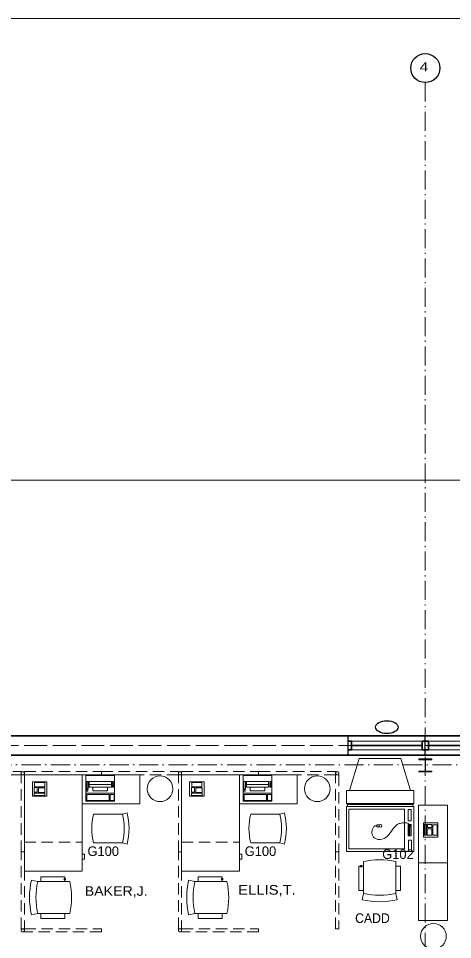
# Model space of a CAD drawing. Extents: x -118748 to -117136, y -118748 to -117596.
# Drawn here: x -118262.8 to -118046.3, y -118056 to -117596.4 of the extents above; entities that cross this region are included whole.
import ezdxf
from ezdxf.enums import TextEntityAlignment as Align

# ---------------------------------------------------------------- set-up
doc = ezdxf.new("R2010")
doc.units = 0
doc.header["$LTSCALE"] = 1.9
doc.header["$PDMODE"] = 32
doc.header["$PDSIZE"] = 0.95
for name, pattern in [('DOT_DASHED', [7.7, 5, -1.2, 0.3, -1.2]), ('LONG_DASHED', [7.5, 6, -1.5]), ('MEDIUM_DASHED', [4.5, 3, -1.5])]:
    doc.linetypes.add(name, pattern=pattern)
for name, color, linetype, lineweight in [('10', 7, 'DOT_DASHED', 13), ('11', 7, 'Continuous', 25), ('12', 7, 'Continuous', 13), ('15', 7, 'Continuous', 13), ('16', 7, 'Continuous', 13), ('2', 7, 'Continuous', 35), ('20', 7, 'MEDIUM_DASHED', 13), ('23', 7, 'Continuous', 25), ('3', 7, 'Continuous', 35), ('30', 7, 'Continuous', 13), ('4', 7, 'Continuous', 35), ('43', 7, 'Continuous', 25), ('5', 7, 'Continuous', 13), ('6', 7, 'Continuous', 13), ('60', 7, 'LONG_DASHED', 13), ('9', 7, 'Continuous', 35)]:
    doc.layers.add(name, color=color, linetype=linetype, lineweight=lineweight)
doc.layers.add('53', color=7, linetype='Continuous')

msp = doc.modelspace()

# ---------------------------------------------------------------- linework, layer by layer
at = {"layer": '10'}
for p, q in [((-118059.921, -117628.339), (-118059.921, -118698.41)), ((-118641.571, -117968.81), (-117285.521, -117968.81))]:
    msp.add_line(p, q, dxfattribs=at)
at = {"layer": '11'}
msp.add_circle((-118059.921, -117621.139), 7.253, dxfattribs=at)
at = {"layer": '12'}
msp.add_lwpolyline([(-118063.104, -117972.362), (-118056.688, -117972.362), (-118056.688, -117971.966), (-118059.772, -117971.966), (-118059.772, -117966.262), (-118056.688, -117966.262), (-118056.688, -117965.866), (-118063.104, -117965.866), (-118063.104, -117966.262), (-118060.02, -117966.262), (-118060.02, -117971.966), (-118063.104, -117971.966)], close=True, dxfattribs=at)
at = {"layer": '15', "lineweight": 25}
for p, q in [((-118098.321, -117954.41), (-118506.321, -117954.41)), ((-118098.321, -117964.01), (-118098.321, -117954.41)), ((-118059.921, -117964.01), (-118059.921, -117954.41)), ((-118059.921, -117964.01), (-118059.921, -117954.41))]:
    msp.add_line(p, q, dxfattribs=at)
at = {"layer": '15'}
for p, q in [((-118225.326, -117993.398), (-118210.926, -117993.398)), ((-118210.926, -117993.398), (-118208.604, -117992.791)), ((-118146.926, -117993.398), (-118132.526, -117993.398)), ((-118132.526, -117993.398), (-118130.204, -117992.791)), ((-118210.926, -118007.798), (-118225.326, -118007.798)), ((-118210.926, -118007.798), (-118208.604, -118008.404)), ((-118132.526, -118007.798), (-118146.926, -118007.798)), ((-118132.526, -118007.798), (-118130.204, -118008.404)), ((-118090.667, -118017.075), (-118090.667, -118033.075)), ((-118074.667, -118017.075), (-118074.667, -118033.075)), ((-118093.067, -118019.475), (-118093.067, -118031.475)), ((-118090.667, -118019.475), (-118093.067, -118019.475)), ((-118090.667, -118019.475), (-118090.667, -118031.475)), ((-118074.667, -118019.475), (-118074.667, -118031.475)), ((-118072.267, -118019.475), (-118074.667, -118019.475)), ((-118072.267, -118019.475), (-118072.267, -118031.475)), ((-118253.199, -118027.04), (-118256.327, -118026.364)), ((-118237.199, -118027.04), (-118253.199, -118027.04)), ((-118239.599, -118024.64), (-118251.599, -118024.64)), ((-118251.599, -118024.64), (-118251.599, -118027.04)), ((-118239.599, -118027.04), (-118251.599, -118027.04)), ((-118239.599, -118027.04), (-118239.599, -118024.64)), ((-118174.799, -118027.04), (-118177.927, -118026.364)), ((-118158.799, -118027.04), (-118174.799, -118027.04)), ((-118161.199, -118024.64), (-118173.199, -118024.64)), ((-118173.199, -118024.64), (-118173.199, -118027.04)), ((-118161.199, -118027.04), (-118173.199, -118027.04)), ((-118161.199, -118027.04), (-118161.199, -118024.64)), ((-118093.067, -118031.475), (-118090.667, -118031.475)), ((-118074.667, -118031.475), (-118072.267, -118031.475)), ((-118090.667, -118033.075), (-118091.343, -118036.203)), ((-118074.667, -118033.075), (-118073.99, -118036.203)), ((-118253.199, -118043.04), (-118256.327, -118043.716)), ((-118237.199, -118043.04), (-118253.199, -118043.04)), ((-118239.599, -118043.04), (-118251.599, -118043.04)), ((-118251.599, -118043.04), (-118251.599, -118045.44)), ((-118239.599, -118045.44), (-118251.599, -118045.44)), ((-118239.599, -118045.44), (-118239.599, -118043.04)), ((-118174.799, -118043.04), (-118177.927, -118043.716)), ((-118158.799, -118043.04), (-118174.799, -118043.04)), ((-118161.199, -118043.04), (-118173.199, -118043.04)), ((-118173.199, -118043.04), (-118173.199, -118045.44)), ((-118161.199, -118045.44), (-118173.199, -118045.44)), ((-118161.199, -118045.44), (-118161.199, -118043.04))]:
    msp.add_line(p, q, dxfattribs=at)
at = {"layer": '15', "lineweight": 25}
msp.add_lwpolyline([(-118098.321, -117964.01), (-118496.721, -117964.01), (-118496.721, -117992.81)], dxfattribs=at)
at = {"layer": '15'}
for points in [[(-118259.812, -118021.839), (-118231.012, -118021.839), (-118231.012, -117973.839), (-118259.812, -117973.839)], [(-118231.012, -117988.239), (-118202.212, -117988.239), (-118202.212, -117973.839), (-118231.012, -117973.839)], [(-118181.412, -118021.839), (-118152.612, -118021.839), (-118152.612, -117973.839), (-118181.412, -117973.839)], [(-118152.612, -117988.239), (-118123.812, -117988.239), (-118123.812, -117973.839), (-118152.612, -117973.839)], [(-118063.307, -117988.887), (-118063.307, -118017.687), (-118048.907, -118017.687), (-118048.907, -117988.887)], [(-118063.307, -118017.687), (-118063.307, -118046.487), (-118048.907, -118046.487), (-118048.907, -118017.687)]]:
    msp.add_lwpolyline(points, close=True, dxfattribs=at)
for centre, radius, start, end in [((-118197.776, -118000.597), 28.475, 165.35367, 194.64632), ((-118238.475, -118000.597), 28.475, 345.35367, 14.64632), ((-118238.475, -118000.597), 30.875, 345.35367, 14.64632), ((-118119.376, -118000.597), 28.475, 165.35367, 194.64632), ((-118160.075, -118000.597), 28.475, 345.35367, 14.64632), ((-118160.075, -118000.597), 30.875, 345.35367, 14.64632), ((-118082.667, -118054.083), 37.863, 77.80217, 102.19783), ((-118216.19, -118035.04), 41.063, 167.80217, 192.19782), ((-118216.19, -118035.04), 37.863, 167.80217, 192.19782), ((-118216.19, -118035.04), 37.863, 167.80217, 192.19782), ((-118274.207, -118035.04), 37.863, 347.80217, 12.19783), ((-118137.79, -118035.04), 41.063, 167.80217, 192.19782), ((-118137.79, -118035.04), 37.863, 167.80217, 192.19782), ((-118137.79, -118035.04), 37.863, 167.80217, 192.19782), ((-118195.807, -118035.04), 37.863, 347.80217, 12.19783), ((-118082.667, -117996.067), 41.063, 257.80217, 282.19783), ((-118082.667, -117996.067), 37.863, 257.80217, 282.19783), ((-118082.667, -117996.067), 37.863, 257.80217, 282.19783)]:
    msp.add_arc(centre, radius, start, end, dxfattribs=at)
for p in [(-118091.867, -118019.475), (-118239.599, -118025.84), (-118161.199, -118025.84)]:
    msp.add_point(p, dxfattribs=at)
at = {"layer": '16'}
for p, q in [((-118098.321, -117954.41), (-118059.921, -117954.41)), ((-118096.721, -117957.027), (-118061.521, -117957.027)), ((-118059.921, -117954.41), (-118021.521, -117954.41)), ((-118058.321, -117957.027), (-118023.121, -117957.027)), ((-118061.521, -117961.391), (-118096.721, -117961.391)), ((-118023.121, -117961.391), (-118058.321, -117961.391)), ((-118059.921, -117964.01), (-118098.321, -117964.01)), ((-118097.634, -117981.701), (-118092.834, -117965.701)), ((-118092.834, -117965.701), (-118072.034, -117965.701)), ((-118067.234, -117981.701), (-118072.034, -117965.701)), ((-118021.521, -117964.01), (-118059.921, -117964.01)), ((-118229.215, -117983.025), (-118214.815, -117983.025)), ((-118150.815, -117983.025), (-118136.415, -117983.025)), ((-118098.651, -117988.635), (-118099.234, -117988.101)), ((-118066.198, -117988.635), (-118065.634, -117988.101))]:
    msp.add_line(p, q, dxfattribs=at)
at = {"layer": '16', "lineweight": 35}
for p, q in [((-118096.721, -117959.209), (-118061.521, -117959.209)), ((-118058.321, -117959.209), (-118023.121, -117959.209))]:
    msp.add_line(p, q, dxfattribs=at)
for points in [[(-118098.321, -117957.027), (-118096.721, -117957.027), (-118096.721, -117961.391), (-118098.321, -117961.391)], [(-118059.921, -117957.027), (-118061.521, -117957.027), (-118061.521, -117961.391), (-118059.921, -117961.391)], [(-118059.921, -117957.027), (-118058.321, -117957.027), (-118058.321, -117961.391), (-118059.921, -117961.391)]]:
    msp.add_lwpolyline(points, dxfattribs=at)
at = {"layer": '16'}
for points in [[(-118229.215, -117987.025), (-118229.215, -117974.225), (-118214.815, -117974.225), (-118214.815, -117987.025)], [(-118150.815, -117987.025), (-118150.815, -117974.225), (-118136.415, -117974.225), (-118136.415, -117987.025)], [(-118248.627, -117984.461), (-118255.827, -117984.461), (-118255.827, -117977.261), (-118248.627, -117977.261)], [(-118254.876, -117982.505), (-118253.42, -117982.505), (-118253.42, -117980.216), (-118254.876, -117980.216)], [(-118254.793, -117979.842), (-118249.675, -117979.842), (-118249.675, -117977.637), (-118254.793, -117977.637)], [(-118252.754, -117982.588), (-118249.634, -117982.588), (-118249.634, -117980.299), (-118252.754, -117980.299)], [(-118228.841, -117981.99), (-118228.841, -117981.158), (-118228.175, -117981.158), (-118228.175, -117981.99)], [(-118228.757, -117980.742), (-118228.757, -117977.206), (-118228.05, -117977.206), (-118228.05, -117980.742)], [(-118227.551, -117978.704), (-118227.551, -117977.104), (-118216.442, -117977.104), (-118216.442, -117978.704)], [(-118227.551, -117979.91), (-118227.551, -117978.704), (-118216.442, -117978.704), (-118216.442, -117979.91)], [(-118225.637, -117981.783), (-118225.637, -117979.91), (-118218.314, -117979.91), (-118218.314, -117981.783)], [(-118215.818, -117977.123), (-118215.818, -117978.121), (-118215.235, -117978.121), (-118215.235, -117977.123)], [(-118215.818, -117978.704), (-118215.818, -117979.952), (-118215.402, -117979.952), (-118215.402, -117978.704)], [(-118170.227, -117984.461), (-118177.427, -117984.461), (-118177.427, -117977.261), (-118170.227, -117977.261)], [(-118176.476, -117982.505), (-118175.02, -117982.505), (-118175.02, -117980.216), (-118176.476, -117980.216)], [(-118176.393, -117979.842), (-118171.275, -117979.842), (-118171.275, -117977.637), (-118176.393, -117977.637)], [(-118174.354, -117982.588), (-118171.234, -117982.588), (-118171.234, -117980.299), (-118174.354, -117980.299)], [(-118150.441, -117981.99), (-118150.441, -117981.158), (-118149.775, -117981.158), (-118149.775, -117981.99)], [(-118150.357, -117980.742), (-118150.357, -117977.206), (-118149.65, -117977.206), (-118149.65, -117980.742)], [(-118149.151, -117978.704), (-118149.151, -117977.104), (-118138.042, -117977.104), (-118138.042, -117978.704)], [(-118149.151, -117979.91), (-118149.151, -117978.704), (-118138.042, -117978.704), (-118138.042, -117979.91)], [(-118147.237, -117981.783), (-118147.237, -117979.91), (-118139.914, -117979.91), (-118139.914, -117981.783)], [(-118137.418, -117977.123), (-118137.418, -117978.121), (-118136.835, -117978.121), (-118136.835, -117977.123)], [(-118137.418, -117978.704), (-118137.418, -117979.952), (-118137.001, -117979.952), (-118137.001, -117978.704)], [(-118249.634, -117983.004), (-118254.876, -117983.004), (-118254.876, -117984.086), (-118249.634, -117984.086)], [(-118228.674, -117983.572), (-118228.674, -117986.567), (-118217.482, -117986.567), (-118217.482, -117983.572)], [(-118217.066, -117983.655), (-118217.066, -117986.609), (-118215.069, -117986.609), (-118215.069, -117983.655)], [(-118171.234, -117983.004), (-118176.476, -117983.004), (-118176.476, -117984.086), (-118171.234, -117984.086)], [(-118150.274, -117983.572), (-118150.274, -117986.567), (-118139.082, -117986.567), (-118139.082, -117983.572)], [(-118138.666, -117983.655), (-118138.666, -117986.609), (-118136.669, -117986.609), (-118136.669, -117983.655)], [(-118099.234, -117988.101), (-118099.234, -117981.701), (-118065.634, -117981.701), (-118065.634, -117988.101)], [(-118099.234, -118012.101), (-118099.234, -117989.701), (-118065.634, -117989.701), (-118065.634, -118012.101)], [(-118098.651, -117989.701), (-118098.651, -117988.635), (-118066.198, -117988.635), (-118066.198, -117989.701)], [(-118098.069, -118010.769), (-118098.069, -117990.881), (-118070.275, -117990.881), (-118070.275, -118010.769)], [(-118068.445, -117991.131), (-118068.445, -117996.789), (-118066.947, -117996.789), (-118066.947, -117991.131)], [(-118084.053, -117998.806), (-118084.053, -117999.805), (-118082.971, -117999.805), (-118082.971, -117998.806)], [(-118068.445, -117998.537), (-118068.445, -118004.195), (-118066.947, -118004.195), (-118066.947, -117998.537)], [(-118068.176, -117998.92), (-118068.176, -117999.587), (-118067.192, -117999.587), (-118067.192, -117998.92)], [(-118060.82, -118004.93), (-118060.82, -117997.73), (-118053.62, -117997.73), (-118053.62, -118004.93)], [(-118059.363, -118003.924), (-118059.363, -117998.682), (-118060.445, -117998.682), (-118060.445, -118003.924)], [(-118058.864, -117998.682), (-118058.864, -118000.138), (-118056.576, -118000.138), (-118056.576, -117998.682)], [(-118056.201, -117998.765), (-118056.201, -118003.882), (-118053.996, -118003.882), (-118053.996, -117998.765)], [(-118068.112, -117999.968), (-118068.112, -118003.81), (-118067.604, -118003.81), (-118067.604, -117999.968)], [(-118058.947, -118000.803), (-118058.947, -118003.924), (-118056.659, -118003.924), (-118056.659, -118000.803)], [(-118068.361, -118006.359), (-118068.361, -118012.018), (-118066.863, -118012.018), (-118066.863, -118006.359)]]:
    msp.add_lwpolyline(points, close=True, dxfattribs=at)
msp.add_circle((-118082.27, -117999.309), 0.671, dxfattribs=at)
msp.add_spline([(-118067.696, -117999.369), (-118067.779, -117998.87), (-118068.528, -117998.038), (-118069.609, -117997.705), (-118072.023, -117997.955), (-118072.938, -117998.121), (-118074.269, -117998.87), (-118079.346, -118004.861), (-118080.927, -118005.777), (-118082.341, -118006.109), (-118083.173, -118006.109), (-118083.922, -118005.943), (-118085.42, -118005.194), (-118085.919, -118004.612), (-118086.502, -118003.114), (-118086.419, -118001.616), (-118086.252, -118000.867), (-118085.503, -117999.619), (-118085.004, -117999.203), (-118084.338, -117999.203), (-118084.172, -117999.203), (-118084.089, -117999.286)], degree=3, dxfattribs=at)
at = {"layer": '2', "lineweight": 13}
msp.add_lwpolyline([(-118748.365, -118748.365), (-117365.965, -118748.365), (-117365.965, -117826.765), (-118748.365, -117826.765), (-118748.365, -118748.365), (-117135.565, -118748.365), (-117135.565, -117596.365), (-118748.365, -117596.365)], close=True, dxfattribs=at)
at = {"layer": '20'}
for points in [[(-118299.812, -117973.839), (-118299.812, -117972.239), (-118261.412, -117972.239), (-118261.412, -117973.839)], [(-118259.812, -117973.839), (-118259.812, -117972.239), (-118221.412, -117972.239), (-118221.412, -117973.839)], [(-118221.412, -117973.839), (-118221.412, -117972.239), (-118183.012, -117972.239), (-118183.012, -117973.839)], [(-118181.412, -117973.839), (-118181.412, -117972.239), (-118143.012, -117972.239), (-118143.012, -117973.839)], [(-118143.012, -117973.839), (-118143.012, -117972.239), (-118104.612, -117972.239), (-118104.612, -117973.839)], [(-118261.412, -117973.839), (-118259.812, -117973.839), (-118259.812, -118012.239), (-118261.412, -118012.239)], [(-118261.412, -117973.839), (-118259.812, -117973.839), (-118259.812, -118012.239), (-118261.412, -118012.239)], [(-118183.012, -117973.839), (-118181.412, -117973.839), (-118181.412, -118012.239), (-118183.012, -118012.239)], [(-118183.012, -117973.839), (-118181.412, -117973.839), (-118181.412, -118012.239), (-118183.012, -118012.239)], [(-118104.612, -117973.839), (-118103.012, -117973.839), (-118103.012, -118012.239), (-118104.612, -118012.239)], [(-118261.412, -118012.239), (-118259.812, -118012.239), (-118259.812, -118050.639), (-118261.412, -118050.639)], [(-118261.412, -118012.239), (-118259.812, -118012.239), (-118259.812, -118050.639), (-118261.412, -118050.639)], [(-118183.012, -118012.239), (-118181.412, -118012.239), (-118181.412, -118050.639), (-118183.012, -118050.639)], [(-118183.012, -118012.239), (-118181.412, -118012.239), (-118181.412, -118050.639), (-118183.012, -118050.639)], [(-118104.612, -118012.239), (-118103.012, -118012.239), (-118103.012, -118050.639), (-118104.612, -118050.639)], [(-118259.812, -118052.239), (-118259.812, -118050.639), (-118221.412, -118050.639), (-118221.412, -118052.239)], [(-118181.412, -118052.239), (-118181.412, -118050.639), (-118143.012, -118050.639), (-118143.012, -118052.239)]]:
    msp.add_lwpolyline(points, close=True, dxfattribs=at)
for centre in [(-118260.612, -117973.039), (-118260.612, -117973.039), (-118182.212, -117973.039), (-118182.212, -117973.039), (-118103.812, -117973.039), (-118260.612, -118051.439), (-118182.212, -118051.439)]:
    msp.add_circle(centre, 0.8, dxfattribs=at)
at = {"layer": '23', "linetype": 'MEDIUM_DASHED', "lineweight": 13}
for points in [[(-118231.012, -118021.839), (-118259.812, -118021.839), (-118259.812, -118007.439), (-118231.012, -118007.439)], [(-118152.612, -118021.839), (-118181.412, -118021.839), (-118181.412, -118007.439), (-118152.612, -118007.439)], [(-118231.012, -118015.839), (-118229.812, -118015.839), (-118229.812, -118013.439), (-118231.012, -118013.439)], [(-118152.612, -118015.839), (-118151.412, -118015.839), (-118151.412, -118013.439), (-118152.612, -118013.439)]]:
    msp.add_lwpolyline(points, close=True, dxfattribs=at)
at = {"layer": '3'}
msp.add_lwpolyline([(-118595.921, -118352.81), (-118595.921, -118170.41), (-118506.321, -118170.41), (-118506.321, -117954.41), (-118098.321, -117954.41), (-117829.521, -117954.41)], dxfattribs=at)
at = {"layer": '30'}
for centre in [(-118192.163, -117980.776), (-118113.763, -117980.776), (-118055.846, -118054.383)]:
    msp.add_circle(centre, 6.4, dxfattribs=at)
at = {"layer": '4'}
msp.add_lwpolyline([(-118496.721, -117964.01), (-118496.721, -118636.01), (-118271.121, -118636.01), (-118271.121, -118588.01), (-118115.969, -118588.01), (-118106.1, -118586.234), (-118096.66, -118581.314), (-118089.115, -118573.804), (-118084.156, -118564.399), (-118081.154, -118548.633), (-118079.134, -118548.633), (-117884.057, -118548.587), (-117881.646, -118565.336), (-117876.897, -118574.111), (-117869.271, -118581.538), (-117859.789, -118586.351), (-117850.271, -118588.01), (-117695.121, -118588.01), (-117695.121, -118636.01), (-117469.521, -118636.01), (-117469.521, -117964.01)], close=True, dxfattribs=at)
at = {"layer": '43'}
msp.add_ellipse((-118079.121, -117950.01), major_axis=(-5.6, 0), ratio=0.571429, dxfattribs=at)
at = {"layer": '5'}
msp.add_line((-118496.721, -117964.01), (-117986.969, -117964.01), dxfattribs=at)
msp.add_lwpolyline([(-118496.721, -117964.01), (-118098.321, -117964.01), (-117984.721, -117964.01), (-117984.721, -118118.36), (-118059.921, -118118.36)], dxfattribs=at)
at = {"layer": '6'}
msp.add_lwpolyline([(-118496.721, -117964.01), (-117984.721, -117964.01), (-117984.721, -118118.36), (-118059.921, -118118.36)], dxfattribs=at)
at = {"layer": '60'}
msp.add_lwpolyline([(-117464.721, -118175.21), (-117464.721, -117959.21), (-118501.521, -117959.21)], dxfattribs=at)

# ---------------------------------------------------------------- texts
at = {"layer": '11', "width": 1.3}
msp.add_text(' 4 ', height=4.518, dxfattribs=at).set_placement((-118060.601, -117622.84), align=Align.CENTER)
at = {"layer": '53'}
for s, width, p in [('BAKER,J.', 1.1, (-118229.732, -118034.191)), ('ELLIS,T.', 1.15, (-118153.191, -118033.602)), ('CADD', 0.95, (-118094.902, -118047.733))]:
    msp.add_text(s, height=4.8, dxfattribs=dict(at, width=width)).set_placement(p)
at = {"layer": '9'}
for s, p in [('G100', (-118220.503, -118014.325)), ('G100', (-118142.103, -118014.325)), ('G102', (-118073.557, -118015.802))]:
    msp.add_text(s, height=4.8, dxfattribs=at).set_placement(p, align=Align.CENTER)

doc.saveas('drawing.dxf')
